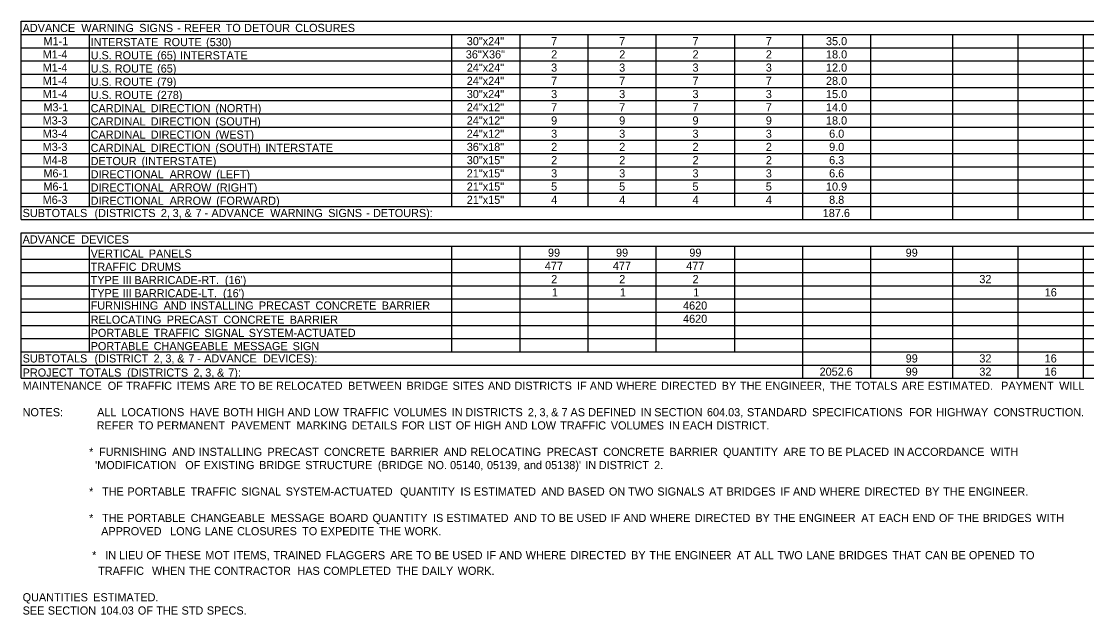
# Model space of a CAD drawing. Extents: x 544250 to 1930787, y -1948365 to 596640.
# Drawn here: x 544454 to 545241, y -1947013 to -1946575 of the extents above; entities that cross this region are included whole.
import ezdxf

# ---------------------------------------------------------------- set-up
doc = ezdxf.new("R2010")
doc.units = 0
doc.layers.add('Default', color=7, linetype='Continuous')

msp = doc.modelspace()

# ---------------------------------------------------------------- linework, layer by layer
at = {"layer": 'Default'}
for p, q in [((544454.39, -1946575.04), (545554.19, -1946575.04)), ((544454.39, -1946575.04), (545554.19, -1946575.04)), ((544454.39, -1946721.29), (544454.39, -1946575.04)), ((544454.39, -1946721.29), (544454.39, -1946575.04)), ((544454.39, -1946584.79), (545554.19, -1946584.79)), ((544504.61, -1946711.54), (544504.61, -1946584.79)), ((544504.61, -1946711.54), (544504.61, -1946584.79)), ((544772.24, -1946711.54), (544772.24, -1946584.79)), ((544772.24, -1946711.54), (544772.24, -1946584.79)), ((544822.46, -1946711.54), (544822.46, -1946584.79)), ((544822.46, -1946711.54), (544822.46, -1946584.79)), ((544872.67, -1946711.54), (544872.67, -1946584.79)), ((544872.67, -1946711.54), (544872.67, -1946584.79)), ((544922.88, -1946711.54), (544922.88, -1946584.79)), ((544922.88, -1946711.54), (544922.88, -1946584.79)), ((544980.89, -1946711.54), (544980.89, -1946584.79)), ((545031.11, -1946711.54), (545031.11, -1946584.79)), ((545031.11, -1946721.29), (545031.11, -1946584.79)), ((545081.32, -1946721.29), (545081.32, -1946584.79)), ((545081.32, -1946721.29), (545081.32, -1946584.79)), ((545141.77, -1946721.29), (545141.77, -1946584.79)), ((545141.77, -1946721.29), (545141.77, -1946584.79)), ((545190.03, -1946721.29), (545190.03, -1946584.79)), ((545190.03, -1946721.29), (545190.03, -1946584.79)), ((545238.29, -1946721.29), (545238.29, -1946584.79)), ((545238.29, -1946721.29), (545238.29, -1946584.79)), ((544454.39, -1946594.54), (545554.19, -1946594.54)), ((544454.39, -1946604.29), (545554.19, -1946604.29)), ((544454.39, -1946614.04), (545554.19, -1946614.04)), ((544454.39, -1946623.79), (545554.19, -1946623.79)), ((544454.39, -1946633.54), (545554.19, -1946633.54)), ((544454.39, -1946643.29), (545554.19, -1946643.29)), ((544454.39, -1946653.04), (545554.19, -1946653.04)), ((544454.39, -1946662.79), (545554.19, -1946662.79)), ((544454.39, -1946672.54), (545554.19, -1946672.54)), ((544454.39, -1946682.29), (545554.19, -1946682.29)), ((544454.39, -1946692.04), (545554.19, -1946692.04)), ((544454.39, -1946701.79), (545554.19, -1946701.79)), ((544454.39, -1946711.54), (545554.19, -1946711.54)), ((544454.39, -1946711.54), (545554.19, -1946711.54)), ((544454.39, -1946721.29), (545554.19, -1946721.29)), ((544454.39, -1946731.04), (545554.19, -1946731.04)), ((544454.39, -1946731.04), (545554.19, -1946731.04)), ((544454.39, -1946838.29), (544454.39, -1946731.04)), ((544454.39, -1946838.29), (544454.39, -1946731.04)), ((544454.39, -1946740.79), (545554.19, -1946740.79)), ((544504.61, -1946779.79), (544504.61, -1946740.79)), ((544504.61, -1946818.79), (544504.61, -1946740.79)), ((544772.24, -1946818.79), (544772.24, -1946740.79)), ((544772.24, -1946818.79), (544772.24, -1946740.79)), ((544822.46, -1946818.79), (544822.46, -1946740.79)), ((544822.46, -1946818.79), (544822.46, -1946740.79)), ((544872.67, -1946818.79), (544872.67, -1946740.79)), ((544872.67, -1946818.79), (544872.67, -1946740.79)), ((544922.88, -1946818.79), (544922.88, -1946740.79)), ((544922.88, -1946818.79), (544922.88, -1946740.79)), ((544980.89, -1946818.79), (544980.89, -1946740.79)), ((545031.11, -1946838.29), (545031.11, -1946740.79)), ((545031.11, -1946838.29), (545031.11, -1946740.79)), ((545081.32, -1946838.29), (545081.32, -1946740.79)), ((545081.32, -1946838.29), (545081.32, -1946740.79)), ((545141.77, -1946838.29), (545141.77, -1946740.79)), ((545141.77, -1946838.29), (545141.77, -1946740.79)), ((545190.03, -1946838.29), (545190.03, -1946740.79)), ((545190.03, -1946838.29), (545190.03, -1946740.79)), ((545238.29, -1946838.29), (545238.29, -1946740.79)), ((545238.29, -1946838.29), (545238.29, -1946740.79)), ((544454.39, -1946750.54), (545554.19, -1946750.54)), ((544454.39, -1946760.29), (545554.19, -1946760.29)), ((544454.39, -1946770.04), (545554.19, -1946770.04)), ((544454.39, -1946779.79), (545554.19, -1946779.79)), ((544454.39, -1946789.54), (544504.61, -1946789.54)), ((544454.39, -1946789.54), (545554.19, -1946789.54)), ((544504.61, -1946818.79), (544504.61, -1946789.54)), ((544772.24, -1946789.54), (544922.88, -1946789.54)), ((544922.88, -1946789.54), (544980.89, -1946789.54)), ((544980.89, -1946789.54), (545238.29, -1946789.54)), ((545238.29, -1946789.54), (545554.19, -1946789.54)), ((544454.39, -1946799.29), (545554.19, -1946799.29)), ((544454.39, -1946809.04), (545554.19, -1946809.04)), ((544980.89, -1946818.79), (544980.89, -1946809.04)), ((544454.39, -1946818.79), (544980.89, -1946818.79)), ((544454.39, -1946818.79), (545554.19, -1946818.79)), ((544980.89, -1946818.79), (545554.19, -1946818.79)), ((544454.39, -1946828.54), (545554.19, -1946828.54)), ((544454.39, -1946838.29), (545554.19, -1946838.29))]:
    msp.add_line(p, q, dxfattribs=at)

# ---------------------------------------------------------------- texts
for s, p in [('ADVANCE', (544455.37, -1946582.92)), (' WARNING', (544496.41, -1946582.92)), (' SIGNS', (544539.21, -1946582.92)), (' -', (544567.22, -1946582.92)), (' REFER', (544572.28, -1946582.92)), (' TO', (544602.98, -1946582.92)), (' DETOUR', (544616.62, -1946582.92)), (' CLOSURES', (544654.31, -1946582.92)), ('M1-1', (544470.72, -1946592.67)), ('INTERSTATE', (544505.58, -1946593.34)), (' ROUTE', (544557.31, -1946593.34)), (' (530)', (544588.53, -1946593.34)), ('30"x24"', (544783.15, -1946592.67)), ('7', (544845.42, -1946592.67)), ('7', (544895.63, -1946592.67)), ('7', (544949.75, -1946592.67)), ('7', (545003.86, -1946592.67)), ('35.0', (545048.26, -1946592.67)), ('M1-4', (544470.16, -1946602.42)), ('U.S.', (544505.58, -1946603.09)), (' ROUTE', (544521.15, -1946603.09)), (' (65)', (544552.38, -1946603.09)), (' INTERSTATE', (544569.3, -1946603.09)), ('36"X36"', (544782.45, -1946602.42)), ('2', (544845.45, -1946602.42)), ('2', (544895.67, -1946602.42)), ('2', (544949.78, -1946602.42)), ('2', (545003.89, -1946602.42)), ('18.0', (545048.26, -1946602.42)), ('M1-4', (544470.16, -1946612.17)), (' (65)', (544552.38, -1946612.84)), ('24"x24"', (544783.15, -1946612.17)), ('3', (544845.42, -1946612.17)), ('3', (544895.63, -1946612.17)), ('3', (544949.75, -1946612.17)), ('3', (545003.86, -1946612.17)), ('12.0', (545048.26, -1946612.17)), ('U.S.', (544505.58, -1946612.84)), (' ROUTE', (544521.15, -1946612.84)), ('M1-4', (544470.16, -1946621.92)), ('U.S.', (544505.58, -1946622.59)), (' ROUTE', (544521.15, -1946622.59)), (' (79)', (544552.38, -1946622.59)), ('24"x24"', (544783.15, -1946621.92)), ('7', (544845.42, -1946621.92)), ('7', (544895.63, -1946621.92)), ('7', (544949.75, -1946621.92)), ('7', (545003.86, -1946621.92)), ('28.0', (545048.26, -1946621.92)), ('M1-4', (544470.16, -1946631.67)), ('U.S.', (544505.58, -1946632.34)), (' ROUTE', (544521.15, -1946632.34)), (' (278)', (544552.38, -1946632.34)), ('30"x24"', (544783.15, -1946631.67)), ('3', (544845.42, -1946631.67)), ('3', (544895.63, -1946631.67)), ('3', (544949.75, -1946631.67)), ('3', (545003.86, -1946631.67)), ('15.0', (545048.26, -1946631.67)), ('M3-1', (544470.72, -1946641.42)), ('CARDINAL', (544505.58, -1946642.09)), (' DIRECTION', (544547.68, -1946642.09)), (' (NORTH)', (544595.43, -1946642.09)), ('24"x12"', (544783.15, -1946641.42)), ('7', (544845.42, -1946641.42)), ('7', (544895.63, -1946641.42)), ('7', (544949.75, -1946641.42)), ('7', (545003.86, -1946641.42)), ('14.0', (545048.26, -1946641.42)), ('M3-3', (544470.14, -1946651.17)), ('CARDINAL', (544505.58, -1946651.84)), (' DIRECTION', (544547.68, -1946651.84)), (' (SOUTH)', (544595.43, -1946651.84)), ('24"x12"', (544783.15, -1946651.17)), ('9', (544845.42, -1946651.17)), ('9', (544895.63, -1946651.17)), ('9', (544949.74, -1946651.17)), ('9', (545003.86, -1946651.17)), ('18.0', (545048.26, -1946651.17)), ('M3-4', (544470.16, -1946660.92)), ('CARDINAL', (544505.58, -1946661.59)), (' DIRECTION', (544547.68, -1946661.59)), (' (WEST)', (544595.43, -1946661.59)), ('24"x12"', (544783.15, -1946660.92)), ('3', (544845.42, -1946660.92)), ('3', (544895.63, -1946660.92)), ('3', (544949.75, -1946660.92)), ('3', (545003.86, -1946660.92)), ('6.0', (545050.59, -1946660.92)), ('M3-3', (544470.14, -1946670.67)), ('CARDINAL', (544505.58, -1946671.34)), (' DIRECTION', (544547.68, -1946671.34)), (' (SOUTH)', (544595.43, -1946671.34)), (' INTERSTATE', (544632.38, -1946671.34)), ('36"x18"', (544783.15, -1946670.67)), ('2', (544845.45, -1946670.67)), ('2', (544895.67, -1946670.67)), ('2', (544949.78, -1946670.67)), ('2', (545003.89, -1946670.67)), ('9.0', (545050.59, -1946670.67)), ('M4-8', (544470.14, -1946680.42)), ('DETOUR', (544505.58, -1946681.09)), (' (INTERSTATE)', (544540.87, -1946681.09)), ('30"x15"', (544783.15, -1946680.42)), ('2', (544845.45, -1946680.42)), ('2', (544895.67, -1946680.42)), ('2', (544949.78, -1946680.42)), ('2', (545003.89, -1946680.42)), ('6.3', (545050.58, -1946680.42)), ('M6-1', (544470.72, -1946690.17)), ('DIRECTIONAL', (544505.58, -1946690.84)), (' ARROW', (544561.65, -1946690.84)), (' (LEFT)', (544596.02, -1946690.84)), ('21"x15"', (544783.15, -1946690.17)), ('3', (544845.42, -1946690.17)), ('3', (544895.63, -1946690.17)), ('3', (544949.75, -1946690.17)), ('3', (545003.86, -1946690.17)), ('6.6', (545050.58, -1946690.17)), ('M6-1', (544470.72, -1946699.92)), ('DIRECTIONAL', (544505.58, -1946700.59)), (' ARROW', (544561.65, -1946700.59)), (' (RIGHT)', (544596.02, -1946700.59)), ('21"x15"', (544783.15, -1946699.92)), ('5', (544845.4, -1946699.92)), ('5', (544895.61, -1946699.92)), ('5', (544949.72, -1946699.92)), ('5', (545003.84, -1946699.92)), ('10.9', (545048.24, -1946699.92)), ('M6-3', (544470.14, -1946709.67)), ('DIRECTIONAL', (544505.58, -1946710.34)), (' ARROW', (544561.65, -1946710.34)), (' (FORWARD)', (544596.02, -1946710.34)), ('21"x15"', (544783.15, -1946709.67)), ('4', (544845.44, -1946709.67)), ('4', (544895.65, -1946709.67)), ('4', (544949.76, -1946709.67)), ('4', (545003.87, -1946709.67)), ('8.8', (545050.57, -1946709.67)), ('SUBTOTALS', (544455.37, -1946719.42)), (' (DISTRICTS', (544506.19, -1946719.42)), (' 2,', (544555.15, -1946719.42)), (' 3,', (544563.86, -1946719.42)), (' &', (544572.57, -1946719.42)), (' 7', (544580.82, -1946719.42)), (' -', (544587.44, -1946719.42)), (' ADVANCE', (544592.5, -1946719.42)), (' WARNING', (544635.87, -1946719.42)), (' SIGNS', (544678.67, -1946719.42)), (' -', (544706.67, -1946719.42)), (' DETOURS):', (544711.73, -1946719.42)), ('187.6', (545045.88, -1946719.42)), ('ADVANCE', (544455.37, -1946738.92)), (' DEVICES', (544496.41, -1946738.92)), ('VERTICAL', (544505.58, -1946749.34)), (' PANELS', (544546.28, -1946749.34)), ('99', (544843.09, -1946748.67)), ('99', (544893.3, -1946748.67)), ('99', (544947.41, -1946748.67)), ('99', (545107.07, -1946748.67)), ('TRAFFIC', (544505.58, -1946759.09)), (' DRUMS', (544540.64, -1946759.09)), ('477', (544840.76, -1946758.42)), ('477', (544890.97, -1946758.42)), ('477', (544945.09, -1946758.42)), ('TYPE', (544505.58, -1946768.84)), (' III', (544527.03, -1946768.84)), (' BARRICADE-RT.', (544535.59, -1946768.84)), (" (16')", (544602.4, -1946768.84)), ('2', (544845.45, -1946768.17)), ('2', (544895.67, -1946768.17)), ('2', (544949.78, -1946768.17)), ('32', (545161.46, -1946768.17)), ('16', (545209.69, -1946777.92)), ('TYPE', (544505.58, -1946778.59)), (' III', (544527.03, -1946778.59)), (' BARRICADE-LT.', (544535.59, -1946778.59)), (" (16')", (544601.01, -1946778.59)), ('1', (544846, -1946777.92)), ('1', (544896.22, -1946777.92)), ('1', (544950.33, -1946777.92)), ('FURNISHING', (544505.58, -1946787.67)), (' AND', (544557.22, -1946787.67)), (' INSTALLING', (544576.8, -1946787.67)), (' PRECAST', (544627.52, -1946787.67)), (' CONCRETE', (544669.28, -1946787.67)), (' BARRIER', (544718.21, -1946787.67)), ('4620', (544942.77, -1946787.67)), ('RELOCATING', (544505.58, -1946798.09)), (' PRECAST', (544559.56, -1946798.09)), (' CONCRETE', (544601.32, -1946798.09)), (' BARRIER', (544650.25, -1946798.09)), ('4620', (544942.77, -1946797.42)), ('PORTABLE', (544505.58, -1946807.84)), (' TRAFFIC', (544549.86, -1946807.84)), (' SIGNAL', (544587.25, -1946807.84)), (' SYSTEM-ACTUATED', (544620.03, -1946807.84)), ('PORTABLE', (544505.58, -1946817.59)), (' CHANGEABLE', (544549.86, -1946817.59)), (' MESSAGE', (544609.05, -1946817.59)), (' SIGN', (544652.4, -1946817.59)), ('SUBTOTALS', (544455.37, -1946826.67)), (' (DISTRICT', (544506.19, -1946826.67)), (' 2,', (544549.8, -1946826.67)), (' 3,', (544558.51, -1946826.67)), (' &', (544567.22, -1946826.67)), (' 7', (544575.46, -1946826.67)), (' -', (544582.08, -1946826.67)), (' ADVANCE', (544587.14, -1946826.67)), (' DEVICES):', (544630.51, -1946826.67)), ('99', (545107.08, -1946826.67)), ('32', (545161.45, -1946826.67)), ('16', (545209.65, -1946826.67)), ('PROJECT', (544455.37, -1946837.09)), (' TOTALS', (544494.79, -1946837.09)), (' (DISTRICTS', (544530.25, -1946837.09)), (' 2,', (544579.2, -1946837.09)), (' 3,', (544587.91, -1946837.09)), (' &', (544596.62, -1946837.09)), (' 7):', (544604.87, -1946837.09)), ('2052.6', (545043.55, -1946836.42)), ('99', (545107.08, -1946836.42)), ('32', (545161.45, -1946836.42)), ('16', (545209.65, -1946836.42)), ('MAINTENANCE', (544455.37, -1946846.84)), (' OF', (544515.94, -1946846.84)), (' TRAFFIC', (544529.53, -1946846.84)), (' ITEMS', (544566.92, -1946846.84)), (' ARE', (544594.43, -1946846.84)), (' TO', (544613.55, -1946846.84)), (' BE', (544627.15, -1946846.84)), (' RELOCATED', (544640.21, -1946846.84)), (' BETWEEN', (544693.34, -1946846.84)), (' BRIDGE', (544736.44, -1946846.84)), (' SITES', (544770.46, -1946846.84)), (' AND', (544796.58, -1946846.84)), (' DISTRICTS', (544816.16, -1946846.84)), (' IF', (544862.3, -1946846.84)), (' AND', (544871.7, -1946846.84)), (' WHERE', (544891.28, -1946846.84)), (' DIRECTED', (544924.37, -1946846.84)), (' BY', (544969.1, -1946846.84)), (' THE', (544982.55, -1946846.84)), (' ENGINEER,', (545001.2, -1946846.84)), (' THE', (545048.9, -1946846.84)), (' TOTALS', (545067.55, -1946846.84)), (' ARE', (545102.05, -1946846.84)), (' ESTIMATED.', (545121.17, -1946846.84)), ('  PAYMENT', (545173.08, -1946846.84)), (' WILL', (545218.1, -1946846.84)), ('NOTES:', (544455.37, -1946866.34)), ('           ALL', (544485.85, -1946866.34)), (' LOCATIONS', (544526.07, -1946866.34)), (' HAVE', (544576.41, -1946866.34)), (' BOTH', (544601.12, -1946866.34)), (' HIGH', (544626.06, -1946866.34)), (' AND', (544648.67, -1946866.34)), (' LOW', (544668.25, -1946866.34)), (' TRAFFIC', (544689.58, -1946866.34)), (' VOLUMES', (544726.97, -1946866.34)), (' IN', (544769.86, -1946866.34)), (' DISTRICTS', (544779.88, -1946866.34)), (' 2,', (544826.02, -1946866.34)), (' 3,', (544834.59, -1946866.34)), (' &', (544843.16, -1946866.34)), (' 7', (544850.89, -1946866.34)), (' AS', (544857.5, -1946866.34)), (' DEFINED', (544870.57, -1946866.34)), (' IN', (544909.25, -1946866.34)), (' SECTION', (544919.28, -1946866.34)), (' 604.03,', (544958.18, -1946866.34)), (' STANDARD', (544987.72, -1946866.34)), (' SPECIFICATIONS', (545035.72, -1946866.34)), (' FOR', (545107.49, -1946866.34)), (' HIGHWAY', (545127.4, -1946866.34)), (' CONSTRUCTION.', (545169.72, -1946866.34)), ('  REFER', (544505.58, -1946876.09)), (' TO', (544538.54, -1946876.09)), (' PERMANENT', (544552.14, -1946876.09)), (' PAVEMENT', (544606.94, -1946876.09)), (' MARKING', (544655.22, -1946876.09)), (' DETAILS', (544696.15, -1946876.09)), (' FOR', (544732.98, -1946876.09)), (' LIST', (544752.89, -1946876.09)), (' OF', (544772.75, -1946876.09)), (' HIGH', (544786.34, -1946876.09)), (' AND', (544808.95, -1946876.09)), (' LOW', (544828.53, -1946876.09)), (' TRAFFIC', (544849.86, -1946876.09)), (' VOLUMES', (544887.25, -1946876.09)), (' IN', (544930.14, -1946876.09)), (' EACH', (544940.16, -1946876.09)), (' DISTRICT.', (544965.11, -1946876.09)), ('                      *', (544455.37, -1946895.59)), (' FURNISHING', (544509.55, -1946895.59)), (' AND', (544563.51, -1946895.59)), (' INSTALLING', (544583.1, -1946895.59)), (' PRECAST', (544633.81, -1946895.59)), (' CONCRETE', (544675.58, -1946895.59)), (' BARRIER', (544724.5, -1946895.59)), (' AND', (544763.99, -1946895.59)), (' RELOCATING', (544783.57, -1946895.59)), (' PRECAST', (544839.88, -1946895.59)), (' CONCRETE', (544881.64, -1946895.59)), (' BARRIER', (544930.57, -1946895.59)), (' QUANTITY', (544970.05, -1946895.59)), (' ARE', (545014.7, -1946895.59)), (' TO', (545033.82, -1946895.59)), (' BE', (545047.42, -1946895.59)), (' PLACED', (545060.49, -1946895.59)), (' IN', (545095.91, -1946895.59)), (' ACCORDANCE', (545105.94, -1946895.59)), (' WITH', (545167.45, -1946895.59)), ("                        'MODIFICATION", (544455.37, -1946905.34)), (' OF', (544573.16, -1946905.34)), (' EXISTING', (544586.75, -1946905.34)), (' BRIDGE', (544627.68, -1946905.34)), (' STRUCTURE', (544661.71, -1946905.34)), (' (BRIDGE', (544715.29, -1946905.34)), (' NO.', (544752.1, -1946905.34)), (' 05140,', (544768.6, -1946905.34)), (' 05139,', (544795.81, -1946905.34)), (' and', (544823.02, -1946905.34)), (" 05138)'", (544838.73, -1946905.34)), (' IN', (544868.35, -1946905.34)), (' DISTRICT', (544878.38, -1946905.34)), (' 2.', (544919.19, -1946905.34)), ('                      *', (544455.37, -1946924.84)), ('  THE', (544509.55, -1946924.84)), (' PORTABLE', (544530.52, -1946924.84)), (' TRAFFIC', (544577.13, -1946924.84)), (' SIGNAL', (544614.52, -1946924.84)), (' SYSTEM-ACTUATED', (544647.3, -1946924.84)), (' QUANTITY', (544731.64, -1946924.84)), (' IS', (544776.29, -1946924.84)), (' ESTIMATED', (544786.1, -1946924.84)), (' AND', (544835.96, -1946924.84)), (' BASED', (544855.54, -1946924.84)), (' ON', (544885.85, -1946924.84)), (' TWO', (544900.07, -1946924.84)), (' SIGNALS', (544921.58, -1946924.84)), (' AT', (544959.81, -1946924.84)), (' BRIDGES', (544972.68, -1946924.84)), (' IF', (545012.31, -1946924.84)), (' AND', (545021.7, -1946924.84)), (' WHERE', (545041.28, -1946924.84)), (' DIRECTED', (545074.37, -1946924.84)), (' BY', (545119.1, -1946924.84)), (' THE', (545132.55, -1946924.84)), (' ENGINEER.', (545151.2, -1946924.84)), ('                      *', (544455.37, -1946944.34)), ('  THE', (544509.55, -1946944.34)), (' PORTABLE', (544530.52, -1946944.34)), (' CHANGEABLE', (544577.13, -1946944.34)), (' MESSAGE', (544636.32, -1946944.34)), (' BOARD', (544679.67, -1946944.34)), (' QUANTITY', (544711.37, -1946944.34)), (' IS', (544756.02, -1946944.34)), (' ESTIMATED', (544765.83, -1946944.34)), (' AND', (544815.69, -1946944.34)), (' TO', (544835.28, -1946944.34)), (' BE', (544848.87, -1946944.34)), (' USED', (544861.94, -1946944.34)), (' IF', (544887.11, -1946944.34)), (' AND', (544896.51, -1946944.34)), (' WHERE', (544916.09, -1946944.34)), (' DIRECTED', (544949.18, -1946944.34)), (' BY', (544993.91, -1946944.34)), (' THE', (545007.36, -1946944.34)), (' ENGINEER', (545026.01, -1946944.34)), (' AT', (545072.01, -1946944.34)), (' EACH', (545084.89, -1946944.34)), (' END', (545109.84, -1946944.34)), (' OF', (545129.42, -1946944.34)), (' THE', (545143, -1946944.34)), (' BRIDGES', (545161.65, -1946944.34)), (' WITH', (545201.28, -1946944.34)), ('                          APPROVED', (544455.37, -1946954.09)), (' LONG', (544562.04, -1946954.09)), (' LANE', (544587.6, -1946954.09)), (' CLOSURES', (544611.38, -1946954.09)), (' TO', (544659.39, -1946954.09)), (' EXPEDITE', (544672.99, -1946954.09)), (' THE', (544716.34, -1946954.09)), (' WORK.', (544734.99, -1946954.09)), ('                       *', (544455.37, -1946971.79)), ('  IN', (544511.87, -1946971.79)), (' LIEU', (544524.23, -1946971.79)), (' OF', (544544.51, -1946971.79)), (' THESE', (544558.1, -1946971.79)), (' MOT', (544587.94, -1946971.79)), (' ITEMS,', (544608.72, -1946971.79)), (' TRAINED', (544638.25, -1946971.79)), (' FLAGGERS', (544676.93, -1946971.79)), (' ARE', (544724.48, -1946971.79)), (' TO', (544743.6, -1946971.79)), (' BE', (544757.19, -1946971.79)), (' USED', (544770.26, -1946971.79)), (' IF', (544795.43, -1946971.79)), (' AND', (544804.83, -1946971.79)), (' WHERE', (544824.41, -1946971.79)), (' DIRECTED', (544857.5, -1946971.79)), (' BY', (544902.23, -1946971.79)), (' THE', (544915.68, -1946971.79)), (' ENGINEER', (544934.33, -1946971.79)), (' AT', (544980.34, -1946971.79)), (' ALL', (544993.21, -1946971.79)), (' TWO', (545010.15, -1946971.79)), (' LANE', (545031.66, -1946971.79)), (' BRIDGES', (545055.44, -1946971.79)), (' THAT', (545095.07, -1946971.79)), (' CAN', (545119.12, -1946971.79)), (' BE', (545138.46, -1946971.79)), (' OPENED', (545151.53, -1946971.79)), (' TO', (545188.82, -1946971.79)), ('                         TRAFFIC', (544455.37, -1946983.34)), (' WHEN', (544548.62, -1946983.34)), (' THE', (544575.88, -1946983.34)), (' CONTRACTOR', (544594.53, -1946983.34)), (' HAS', (544655.9, -1946983.34)), (' COMPLETED', (544675.03, -1946983.34)), (' THE', (544729.08, -1946983.34)), (' DAILY', (544747.73, -1946983.34)), (' WORK.', (544774.22, -1946983.34)), ('QUANTITIES', (544455.37, -1947002.84)), (' ESTIMATED.', (544505.24, -1947002.84)), ('SEE', (544455.37, -1947012.59)), (' SECTION', (544471.7, -1947012.59)), (' 104.03', (544510.61, -1947012.59)), (' OF', (544538.18, -1947012.59)), (' THE', (544551.77, -1947012.59)), (' STD', (544570.42, -1947012.59)), (' SPECS.', (544589.07, -1947012.59))]:
    msp.add_text(s, height=6, dxfattribs=at).set_placement(p)

doc.saveas('drawing.dxf')
